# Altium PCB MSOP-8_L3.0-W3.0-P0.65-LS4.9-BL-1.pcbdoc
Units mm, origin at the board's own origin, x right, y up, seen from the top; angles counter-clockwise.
Board outline 15.76 x 18.3 mm, 2 copper layers (Top Layer, Bottom Layer), stack 0 mm thick; 1 components, 0 nets, 8 pads, 0 vias.
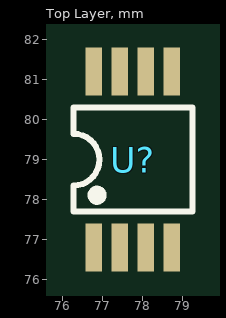
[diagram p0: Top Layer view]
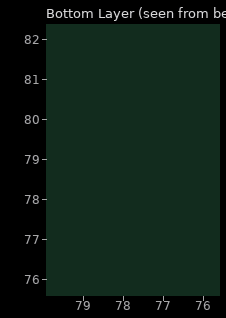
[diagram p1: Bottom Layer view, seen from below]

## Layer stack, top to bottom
Top Layer: signal copper (thickness not stored)
Bottom Layer: signal copper (thickness not stored)

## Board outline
85.61,69.85 69.85,69.85 69.85,88.15 85.61,88.15

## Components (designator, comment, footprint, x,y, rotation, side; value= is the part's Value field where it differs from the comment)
U? "" MSOP-8_L3.0-W3.0-P0.65-LS4.9-BL-1 77.76,79 r0 top

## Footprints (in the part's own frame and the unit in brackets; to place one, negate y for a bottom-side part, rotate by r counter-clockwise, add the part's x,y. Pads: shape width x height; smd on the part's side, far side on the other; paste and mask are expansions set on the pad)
MSOP-8_L3.0-W3.0-P0.65-LS4.9-BL-1 [mm]
  rect 0.406x1.2 smd: 1(-0.975,-2.2) 2(-0.325,-2.2) 3(0.325,-2.2) 4(0.975,-2.2) 5(0.975,2.2) 6(0.325,2.2) 7(-0.325,2.2) 8(-0.975,2.2)
  silkscreen extent -1.48,-1.3 1.5,1.3

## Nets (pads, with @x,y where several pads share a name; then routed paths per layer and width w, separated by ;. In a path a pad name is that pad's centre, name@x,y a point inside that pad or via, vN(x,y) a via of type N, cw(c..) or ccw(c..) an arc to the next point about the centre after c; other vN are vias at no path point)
pads on no net: U?.1 U?.2 U?.3 U?.4 U?.5 U?.6 U?.7 U?.8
